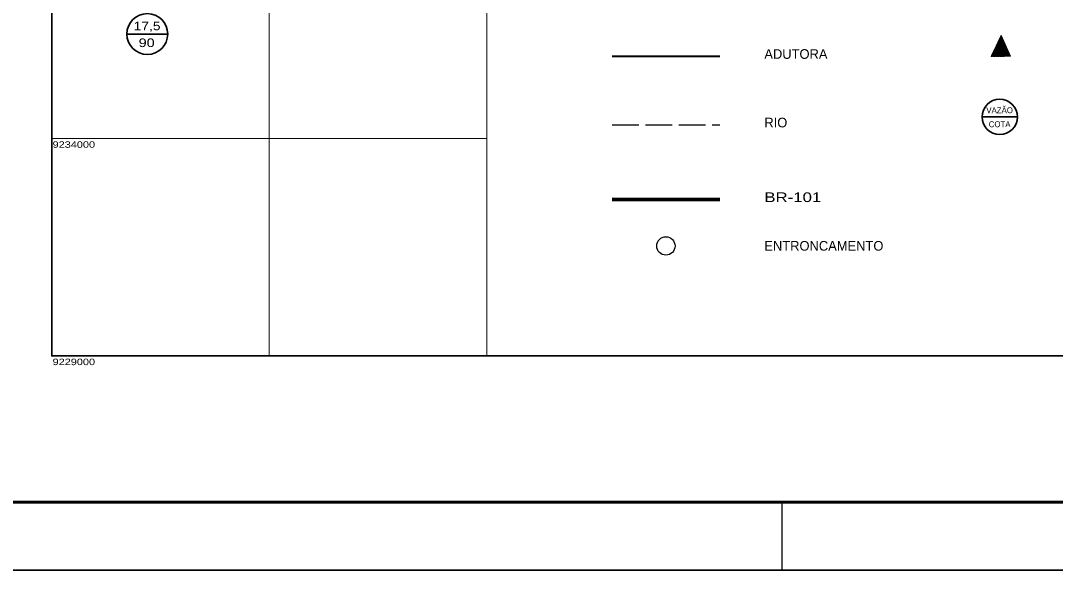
# Model space of a CAD drawing. Extents: x 0 to 1772, y 0 to 1188.
# Drawn here: x 478.7 to 781.9, y -0.1 to 161 of the extents above; entities that cross this region are included whole.
import ezdxf
from ezdxf.enums import TextEntityAlignment as Align

# ---------------------------------------------------------------- set-up
doc = ezdxf.new("R2010")
doc.units = 0
doc.header["$LTSCALE"] = 1.3
doc.linetypes.add('LONG_DASHED', pattern=[7.5, 6, -1.5])
for name, color, linetype, lineweight in [('4', 7, 'Continuous', 13), ('5', 7, 'LONG_DASHED', 25), ('6', 7, 'Continuous', 40), ('63', 7, 'Continuous', 25), ('9', 7, 'Continuous', 40)]:
    doc.layers.add(name, color=color, linetype=linetype, lineweight=lineweight)

msp = doc.modelspace()

# ---------------------------------------------------------------- linework, layer by layer
at = {"layer": '4'}
for p, q in [((763.272, 150.986), (766.946, 154.661)), ((763.376, 151.204), (766.912, 154.739)), ((763.48, 151.421), (766.877, 154.818)), ((763.584, 151.638), (766.842, 154.896)), ((763.688, 151.855), (766.807, 154.974)), ((763.792, 152.072), (766.773, 155.053)), ((763.896, 152.29), (766.738, 155.131)), ((764, 152.507), (766.703, 155.209)), ((764.104, 152.724), (766.668, 155.288)), ((764.209, 152.941), (766.634, 155.366)), ((764.313, 153.158), (766.599, 155.445)), ((764.417, 153.375), (766.564, 155.523)), ((764.521, 153.593), (766.529, 155.601)), ((764.625, 153.81), (766.495, 155.68)), ((764.729, 154.027), (766.46, 155.758)), ((764.833, 154.244), (766.425, 155.836)), ((764.937, 154.461), (766.39, 155.915)), ((765.041, 154.679), (766.356, 155.993)), ((765.145, 154.896), (766.321, 156.072)), ((765.249, 155.113), (766.286, 156.15)), ((765.353, 155.33), (766.251, 156.228)), ((765.457, 155.547), (766.217, 156.307)), ((765.561, 155.764), (766.182, 156.385)), ((765.665, 155.982), (766.147, 156.464)), ((765.769, 156.199), (766.112, 156.542)), ((765.873, 156.416), (766.077, 156.62)), ((765.977, 156.633), (766.043, 156.699)), ((763.064, 150.552), (767.016, 154.504)), ((763.168, 150.769), (766.981, 154.582)), ((763.172, 150.547), (767.051, 154.426)), ((763.286, 150.547), (767.085, 154.347)), ((763.399, 150.548), (767.12, 154.269)), ((763.513, 150.549), (767.155, 154.191)), ((763.627, 150.549), (767.19, 154.112)), ((763.741, 150.55), (767.225, 154.034)), ((763.854, 150.55), (767.259, 153.955)), ((763.968, 150.551), (767.294, 153.877)), ((764.082, 150.552), (767.329, 153.799)), ((764.195, 150.552), (767.364, 153.72)), ((764.309, 150.553), (767.398, 153.642)), ((764.423, 150.553), (767.433, 153.563)), ((764.537, 150.554), (767.468, 153.485)), ((764.65, 150.555), (767.503, 153.407)), ((764.764, 150.555), (767.537, 153.328)), ((764.878, 150.556), (767.572, 153.25)), ((764.992, 150.556), (767.607, 153.172)), ((765.105, 150.557), (767.642, 153.093)), ((765.219, 150.558), (767.676, 153.015)), ((765.333, 150.558), (767.711, 152.936)), ((765.447, 150.559), (767.746, 152.858)), ((765.56, 150.559), (767.781, 152.78)), ((765.674, 150.56), (767.815, 152.701)), ((765.788, 150.561), (767.85, 152.623)), ((765.902, 150.561), (767.885, 152.545)), ((766.015, 150.562), (767.92, 152.466)), ((766.129, 150.562), (767.954, 152.388)), ((766.243, 150.563), (767.989, 152.309)), ((766.357, 150.564), (768.024, 152.231)), ((766.47, 150.564), (768.059, 152.153)), ((766.584, 150.565), (768.093, 152.074)), ((766.698, 150.565), (768.128, 151.996)), ((766.812, 150.566), (768.163, 151.918)), ((766.925, 150.567), (768.198, 151.839)), ((767.039, 150.567), (768.233, 151.761)), ((767.153, 150.568), (768.267, 151.682)), ((767.267, 150.569), (768.302, 151.604)), ((767.38, 150.569), (768.337, 151.526)), ((767.494, 150.57), (768.372, 151.447)), ((767.608, 150.57), (768.406, 151.369)), ((767.721, 150.571), (768.441, 151.291)), ((767.835, 150.572), (768.476, 151.212)), ((767.949, 150.572), (768.511, 151.134)), ((768.063, 150.573), (768.545, 151.055)), ((768.176, 150.573), (768.58, 150.977)), ((768.29, 150.574), (768.615, 150.899)), ((768.404, 150.575), (768.65, 150.82)), ((768.518, 150.575), (768.684, 150.742)), ((768.631, 150.576), (768.719, 150.663)), ((768.745, 150.576), (768.754, 150.585))]:
    msp.add_line(p, q, dxfattribs=at)
at = {"layer": '4', "lineweight": 70}
msp.add_line((652.03, 108.586), (683.603, 108.586), dxfattribs=at)
at = {"layer": '4'}
msp.add_lwpolyline([(763.061, 150.546), (766.026, 156.736), (768.758, 150.576)], close=True, dxfattribs=at)
at = {"layer": '4', "lineweight": 25}
msp.add_ellipse((667.744, 94.984), major_axis=(2.687, 0), ratio=0.998913, dxfattribs=at)
at = {"layer": '5'}
msp.add_line((652.03, 130.478), (683.603, 130.478), dxfattribs=at)
at = {"layer": '6'}
msp.add_line((652.03, 150.576), (683.603, 150.576), dxfattribs=at)
at = {"layer": '63', "lineweight": 13}
for p, q in [((551.534, 62.735), (551.534, 419.523)), ((615.246, 62.735), (615.246, 419.523)), ((615.246, 126.447), (487.822, 126.447))]:
    msp.add_line(p, q, dxfattribs=at)
at = {"layer": '63'}
msp.add_line((701.833, -0.127), (701.833, 19.873), dxfattribs=at)
for points in [[(-0.167, -0.127), (1771.833, -0.127), (1771.833, 1187.873)], [(-0.167, -0.127), (1771.833, -0.127), (-0.167, -0.127)]]:
    msp.add_lwpolyline(points, dxfattribs=at)
at = {"layer": '63', "lineweight": 60}
msp.add_lwpolyline([(49.833, 1167.873), (1751.833, 1167.873), (1751.833, 19.873), (49.833, 19.873)], close=True, dxfattribs=at)
at = {"layer": '63', "lineweight": 35}
msp.add_lwpolyline([(1175.913, 62.735), (487.822, 62.735), (487.822, 419.523)], dxfattribs=at)
at = {"layer": '9', "lineweight": 35}
for p, q in [((509.821, 157.097), (521.791, 157.097)), ((760.391, 132.797), (770.755, 132.797))]:
    msp.add_line(p, q, dxfattribs=at)
for centre, radius in [((515.806, 157.097), 5.985), ((765.573, 132.797), 5.182)]:
    msp.add_circle(centre, radius, dxfattribs=at)

# ---------------------------------------------------------------- texts
at = {"layer": '63'}
for s, p in [('ADUTORA', (696.604, 149.837)), ('RIO', (696.604, 129.738)), ('ENTRONCAMENTO', (696.604, 93.592))]:
    msp.add_text(s, height=2.829, dxfattribs=at).set_placement(p)
for s, height, width, p in [('9234000', 1.911, 1.25, (488.058, 123.744)), ('BR-101', 2.829, 1.3, (696.604, 107.846)), ('9229000', 1.911, 1.25, (488.058, 60.032))]:
    msp.add_text(s, height=height, dxfattribs=dict(at, width=width)).set_placement(p)
at = {"layer": '9'}
for s, width, p in [('17,5', 1.2, (515.755, 158.22)), ('90', 1.25, (515.621, 153.291))]:
    msp.add_text(s, height=2.52, rotation=0.17, dxfattribs=dict(at, width=width)).set_placement(p, align=Align.CENTER)
for s, p in [('VAZÃO', (765.542, 133.897)), ('COTA', (765.542, 129.796))]:
    msp.add_text(s, height=1.72, rotation=0.17, dxfattribs=at).set_placement(p, align=Align.CENTER)

doc.saveas('drawing.dxf')
